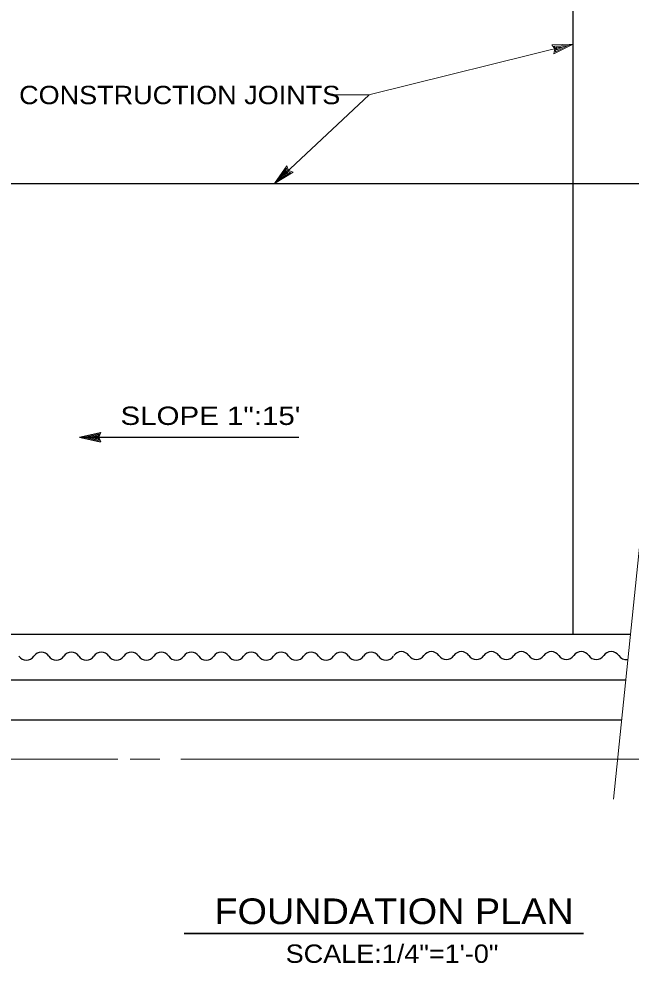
# Model space of a CAD drawing. Extents: x -24.3 to 17.7, y -17.6 to 12.4.
# Drawn here: x -14.6 to -10.43, y -0.56 to 5.87 of the extents above; entities that cross this region are included whole.
import ezdxf
from ezdxf.enums import TextEntityAlignment as Align

# ---------------------------------------------------------------- set-up
doc = ezdxf.new("R2010")
doc.units = 0
doc.header["$LTSCALE"] = 0.05
doc.layers.add('1', color=7, linetype='Continuous', lineweight=13)

msp = doc.modelspace()

# ---------------------------------------------------------------- linework, layer by layer
at = {"layer": '1', "lineweight": 25}
for p, q in [((-10.82769, 1.6764), (-10.82769, 7.8164)), ((-18.37569, 4.7464), (-10.12369, 4.7464)), ((-14.18969, 3.0184), (-14.04569, 3.0494)), ((-14.15269, 3.0184), (-14.05869, 3.0384)), ((-14.11669, 3.0184), (-14.07169, 3.0284)), ((-14.07169, 3.0284), (-14.07569, 3.0184)), ((-14.05869, 3.0384), (-14.06769, 3.0184)), ((-14.18969, 3.0184), (-12.69669, 3.0184)), ((-14.18969, 3.0184), (-14.04569, 2.9874)), ((-14.15269, 3.0184), (-14.05869, 2.9984)), ((-14.11669, 3.0184), (-14.07169, 3.0094)), ((-14.07569, 3.0184), (-14.07169, 3.0094)), ((-14.06769, 3.0184), (-14.05869, 2.9984)), ((-18.37569, 1.6764), (-10.43869, 1.6764)), ((-18.37569, 1.3644), (-10.47069, 1.3644)), ((-18.42869, 1.0934), (-10.49869, 1.0934))]:
    msp.add_line(p, q, dxfattribs=at)
at = {"layer": '1'}
for p, q in [((-12.21869, 5.3504), (-10.82769, 5.6944)), ((-10.82769, 5.6944), (-10.97469, 5.6904)), ((-10.82769, 5.6944), (-10.95969, 5.6294)), ((-10.86369, 5.6854), (-10.95969, 5.6824)), ((-10.94569, 5.6654), (-10.95969, 5.6824)), ((-10.86369, 5.6854), (-10.94969, 5.6434)), ((-10.94969, 5.6434), (-10.94569, 5.6654)), ((-10.89869, 5.6764), (-10.94469, 5.6744)), ((-10.93869, 5.6674), (-10.94469, 5.6744)), ((-10.89869, 5.6764), (-10.93969, 5.6564)), ((-10.93969, 5.6564), (-10.93869, 5.6674)), ((-12.21769, 5.3504), (-12.86169, 4.7464)), ((-12.45569, 5.3504), (-12.21769, 5.3504)), ((-12.86169, 4.7464), (-12.77769, 4.8674)), ((-12.83469, 4.7714), (-12.77969, 4.8504)), ((-12.80869, 4.7964), (-12.78269, 4.8344)), ((-12.78269, 4.8344), (-12.77869, 4.8244)), ((-12.77969, 4.8504), (-12.77269, 4.8294)), ((-12.77869, 4.8244), (-12.76969, 4.8204)), ((-12.77269, 4.8294), (-12.75269, 4.8214)), ((-12.86169, 4.7464), (-12.73569, 4.8224)), ((-12.83469, 4.7714), (-12.75269, 4.8214)), ((-12.80869, 4.7964), (-12.76969, 4.8204)), ((-10.55369, 0.5514), (-10.27869, 3.2364)), ((-17.76969, 0.8254), (-13.92869, 0.8254)), ((-13.84369, 0.8254), (-13.64269, 0.8254)), ((-13.49969, 0.8254), (-9.12369, 0.8254))]:
    msp.add_line(p, q, dxfattribs=at)
at = {"layer": '1', "lineweight": 35}
msp.add_line((-13.47669, -0.3626), (-10.75769, -0.3626), dxfattribs=at)
at = {"layer": '1'}
for points in [[(-10.95969, 5.6294), (-10.95369, 5.6634), (-10.97469, 5.6904)], [(-12.77769, 4.8674), (-12.76669, 4.8354), (-12.73569, 4.8224)]]:
    msp.add_lwpolyline(points, dxfattribs=at)
at = {"layer": '1', "lineweight": 25}
msp.add_lwpolyline([(-14.04569, 3.0494), (-14.05969, 3.0184), (-14.04569, 2.9874)], dxfattribs=at)
for centre, start, end in [((-14.44869, 1.4919), 34.0772, 145.92281), ((-14.24469, 1.4919), 34.0772, 145.92281), ((-14.04069, 1.4919), 34.0772, 145.92281), ((-13.83669, 1.4919), 34.0772, 145.92281), ((-13.63269, 1.4919), 34.0772, 145.92281), ((-13.42869, 1.4919), 34.0772, 145.92281), ((-13.22469, 1.4919), 34.0772, 145.92281), ((-13.02069, 1.4919), 34.0772, 145.92281), ((-12.81669, 1.4919), 34.0772, 145.92281), ((-12.61269, 1.4919), 34.0772, 145.92281), ((-12.40869, 1.4919), 34.0772, 145.92281), ((-12.20469, 1.4919), 34.0772, 145.92281), ((-11.99769, 1.4959), 34.0772, 145.92281), ((-11.79369, 1.4959), 34.0772, 145.92281), ((-11.58969, 1.4959), 34.0772, 145.92281), ((-11.38569, 1.4959), 34.0772, 145.92281), ((-11.18169, 1.4959), 34.0772, 145.92281), ((-10.97769, 1.4959), 34.0772, 145.92281), ((-10.77369, 1.4959), 34.0772, 145.92281), ((-10.56969, 1.4959), 34.0772, 145.92281), ((-14.55069, 1.5609), 214.0772, 325.92281), ((-14.34669, 1.5609), 214.0772, 325.92281), ((-14.14269, 1.5609), 214.0772, 325.92281), ((-13.93869, 1.5609), 214.0772, 325.92281), ((-13.73469, 1.5609), 214.0772, 325.92281), ((-13.53069, 1.5609), 214.0772, 325.92281), ((-13.32669, 1.5609), 214.0772, 325.92281), ((-13.12269, 1.5609), 214.0772, 325.92281), ((-12.91869, 1.5609), 214.0772, 325.92281), ((-12.71469, 1.5609), 214.0772, 325.92281), ((-12.51069, 1.5609), 214.0772, 325.92281), ((-12.30669, 1.5609), 214.0772, 325.92281), ((-12.10269, 1.5609), 214.0772, 325.92281), ((-11.89569, 1.5649), 214.0772, 325.92281), ((-11.69169, 1.5649), 214.0772, 325.92281), ((-11.48769, 1.5649), 214.0772, 325.92281), ((-11.28369, 1.5649), 214.0772, 325.92281), ((-11.07969, 1.5649), 214.0772, 325.92281), ((-10.87569, 1.5649), 214.0772, 325.92281), ((-10.67169, 1.5649), 214.0772, 325.92281), ((-10.46769, 1.5649), 214.0772, 277.0626)]:
    msp.add_arc(centre, 0.06157, start, end, dxfattribs=at)

# ---------------------------------------------------------------- texts
at = {"layer": '1'}
for s, height, width, p in [('CONSTRUCTION JOINTS', 0.125, 1.1, (-13.50719, 5.2864)), ('SLOPE 1":15\'', 0.125, 1.2, (-13.29769, 3.1014)), ('FOUNDATION PLAN', 0.175, 1.1, (-12.04769, -0.2986))]:
    msp.add_text(s, height=height, dxfattribs=dict(at, width=width)).set_placement(p, align=Align.CENTER)
at = {"layer": '1', "width": 1.1}
msp.add_text('SCALE:1/4"=1\'-0"', height=0.125, dxfattribs=at).set_placement((-12.78569, -0.5626))

doc.saveas('drawing.dxf')
